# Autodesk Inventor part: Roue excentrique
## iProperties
Shininess: 20.0
Length Units: 11269
Angle Units: 11279
Time Units: 11290
Mass Units: 11283
Length Display Precision: 3
Angle Display Precision: 2
Created: 2002-05
Part Number: Roue excentrique
Material: Par défaut
Document SubType Name: Modélisation
Designer: Flavien MARTY
Density: 0.0
Volumn: 0.0
Area: 0.0
PropertySet Name: Model Information
Control State: 0
Master: False
Checked Out: False
Author: Flavien MARTY
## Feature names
1. Extrusion1
2. Extrusion2
3. Perçage1 [Hole]
4. Extrusion4
5. Congé2 [Fillet]
